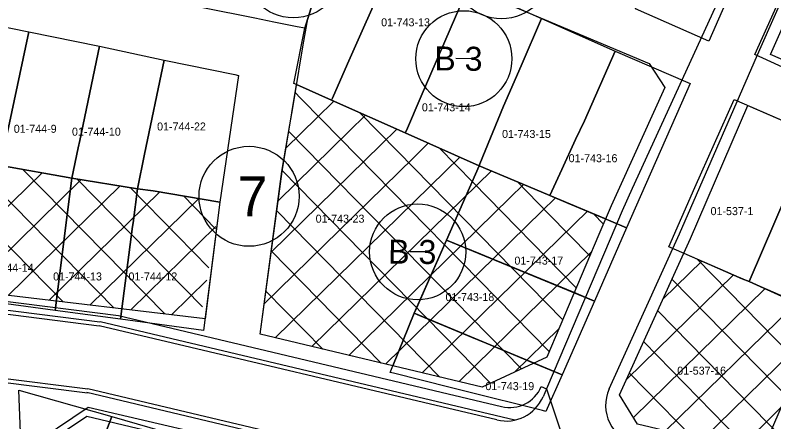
# Model space of a CAD drawing. Extents: x 413946 to 415528, y 4453939 to 4454944.
# Drawn here: x 414976 to 415070.8, y 4454449.6 to 4454500.5 of the extents above; entities that cross this region are included whole.
import ezdxf

# ---------------------------------------------------------------- set-up
doc = ezdxf.new("R2010")
doc.units = 0
for name, color, linetype in [('0_KADASTRO', 7, 'Continuous'), ('1_DÜZENLEME', 7, 'Continuous'), ('1_PLAN_DEĞİŞİKLİĞİ_ONAMA_SINIRI', 7, 'Continuous'), ('Level 27', 7, 'Continuous'), ('Level 28', 7, 'Continuous'), ('Level 29', 7, 'Continuous'), ('Level 32', 7, 'Continuous'), ('Level 34', 7, 'Continuous'), ('Level 57', 7, 'Continuous'), ('Level 58', 7, 'Continuous'), ('Level 62', 7, 'Continuous')]:
    doc.layers.add(name, color=color, linetype=linetype)

msp = doc.modelspace()

# ---------------------------------------------------------------- linework, layer by layer
at = {"layer": '0_KADASTRO'}
for points in [[(415053.526, 4454501.287), (415053.647, 4454501.564), (415056.611, 4454508.314), (415060.089, 4454516.235), (415061.598, 4454519.673), (415070.714, 4454515.564), (415062.675, 4454497.251)], [(414999.46, 4454501.4), (415000.783, 4454505.769), (415000.999, 4454506.48), (415003.5, 4454514.74), (415009.74, 4454512.95), (415015.95, 4454511.24), (415013.322, 4454502.539), (415012.206, 4454498.844), (415011.23, 4454499.04), (415008.331, 4454499.623), (415005.96, 4454500.1)], [(415010.831, 4454491.947), (415012.206, 4454498.844), (415013.322, 4454502.539), (415015.95, 4454511.24), (415023.668, 4454508.222), (415022.42, 4454505.4), (415017.55, 4454494.39), (415015.65, 4454490.095), (415015.543, 4454489.852), (415011.18, 4454491.792)], [(415015.543, 4454489.852), (415015.65, 4454490.095), (415017.55, 4454494.39), (415022.42, 4454505.4), (415023.668, 4454508.222), (415032.71, 4454504.157), (415031.57, 4454501.52), (415026.75, 4454490.37), (415024.892, 4454486.072), (415024.756, 4454485.756)], [(415024.756, 4454485.756), (415024.892, 4454486.072), (415026.75, 4454490.37), (415031.57, 4454501.52), (415032.71, 4454504.157), (415034.35, 4454503.42), (415041.78, 4454500.08), (415039.22, 4454494.14), (415037.04, 4454489.09), (415034.084, 4454481.889), (415033.987, 4454481.653)], [(415068.455, 4454495.571), (415072.492, 4454504.557), (415081.683, 4454500.61), (415081.14, 4454499.42), (415077.45, 4454491.43)], [(414965.358, 4454483.187), (414966.362, 4454488.021), (414966.55, 4454488.926), (414968.89, 4454500.2), (414977.709, 4454498.402), (414975.15, 4454486.42), (414975.008, 4454485.686), (414974.231, 4454481.676)], [(415033.987, 4454481.653), (415034.084, 4454481.889), (415037.04, 4454489.09), (415039.22, 4454494.14), (415041.78, 4454500.08), (415051, 4454496), (415047.14, 4454487.28), (415046.047, 4454484.925), (415044.3, 4454481.16), (415042.804, 4454477.937), (415040.144, 4454479.058)], [(414974.231, 4454481.676), (414975.008, 4454485.686), (414975.15, 4454486.42), (414977.709, 4454498.402), (414986.53, 4454496.61), (414984.071, 4454484.806), (414983.88, 4454483.892), (414983.09, 4454480.1)], [(414983.09, 4454480.1), (414983.88, 4454483.892), (414984.071, 4454484.806), (414986.53, 4454496.61), (414994.62, 4454494.87), (414992.186, 4454483.115), (414991.286, 4454478.771)], [(415042.804, 4454477.937), (415044.3, 4454481.16), (415046.047, 4454484.925), (415047.14, 4454487.28), (415051, 4454496), (415060.07, 4454492.06), (415060.344, 4454491.941), (415052.417, 4454473.885), (415052.1, 4454474.019), (415049.381, 4454475.165), (415045.077, 4454476.979)], [(414991.286, 4454478.771), (414992.186, 4454483.115), (414994.62, 4454494.87), (415003.45, 4454493.044), (415003.923, 4454492.946), (415001.59, 4454477.09), (414993.24, 4454478.51)], [(415006.61, 4454460.57), (415009.35, 4454480.93), (415011.18, 4454491.792), (415015.543, 4454489.852), (415024.756, 4454485.756), (415033.987, 4454481.653), (415029.907, 4454472.353), (415025.989, 4454463.44), (415025.883, 4454463.199), (415023.215, 4454456.611)], [(415057.69, 4454471.52), (415060.95, 4454478.93), (415065.84, 4454489.93), (415072.79, 4454486.95), (415075.692, 4454485.677), (415067.75, 4454467.15), (415066.87, 4454467.5), (415064.77, 4454468.42)], [(415067.75, 4454467.15), (415075.692, 4454485.677), (415084.758, 4454481.701), (415076.74, 4454463.07)], [(414972.081, 4454464.741), (414972.11, 4454464.98), (414973.586, 4454476.594), (414974.231, 4454481.676), (414983.09, 4454480.1), (414982.505, 4454475.494), (414980.986, 4454463.545)], [(415029.907, 4454472.353), (415033.987, 4454481.653), (415040.144, 4454479.058), (415042.804, 4454477.937), (415045.077, 4454476.979), (415049.381, 4454475.165), (415052.1, 4454474.019), (415052.417, 4454473.885), (415048.39, 4454464.712), (415045.869, 4454465.777), (415035.889, 4454469.892), (415034.199, 4454470.587)], [(414980.986, 4454463.545), (414982.505, 4454475.494), (414983.09, 4454480.1), (414991.286, 4454478.771), (414990.736, 4454474.513), (414990.678, 4454474.059), (414989.179, 4454462.444)], [(414989.179, 4454462.444), (414990.678, 4454474.059), (414990.736, 4454474.513), (414991.286, 4454478.771), (414993.24, 4454478.51), (415001.59, 4454477.09), (414999.56, 4454461.06)], [(415044.348, 4454455.506), (415025.883, 4454463.199), (415029.907, 4454472.353), (415048.39, 4454464.712)], [(415051.54, 4454452.98), (415059.577, 4454470.694), (415064.77, 4454468.42), (415066.87, 4454467.5), (415067.75, 4454467.15), (415076.74, 4454463.07), (415069.241, 4454445.645), (415053.79, 4454449.33)], [(415022.88, 4454455.784), (415023.215, 4454456.611), (415025.883, 4454463.199), (415026.514, 4454462.936), (415033.039, 4454460.218), (415034.844, 4454459.466), (415040.837, 4454456.969), (415044.348, 4454455.506), (415042.339, 4454450.928), (415041.913, 4454451.034), (415032.192, 4454453.46), (415030.364, 4454453.916), (415023.271, 4454455.686)], [(414976.99, 4454439.68), (414976.905, 4454441.941), (414976.47, 4454453.59), (414988.09, 4454450.27), (414983.71, 4454438.76), (414983.18, 4454437.36), (414982.59, 4454437.57)], [(414983.18, 4454437.36), (414983.71, 4454438.76), (414988.09, 4454450.27), (414995.98, 4454447.98), (414991.71, 4454437.66), (414990.46, 4454434.63)]]:
    msp.add_lwpolyline(points, close=True, dxfattribs=at)
at = {"layer": '1_DÜZENLEME'}
for p, q in [((414935.427, 4454468.565), (414986.575, 4454462.133)), ((414935.853, 4454468.008), (414986.513, 4454461.637)), ((415036.212, 4454449.853), (414986.513, 4454461.637)), ((415038.448, 4454449.837), (414986.628, 4454462.123)), ((414942.67, 4454459.088), (414985.087, 4454453.753)), ((414943.096, 4454458.53), (414985.024, 4454453.257)), ((415039.929, 4454440.75), (414985.087, 4454453.753)), ((415059.307, 4454435.642), (414984.971, 4454453.267))]:
    msp.add_line(p, q, dxfattribs=at)
msp.add_lwpolyline([(415042.389, 4454453.755), (415041.967, 4454452.762)], dxfattribs=at)
msp.add_arc((415037.365, 4454454.718), 5, 256.66157, 336.96465, dxfattribs=at)
at = {"layer": '1_PLAN_DEĞİŞİKLİĞİ_ONAMA_SINIRI'}
for p, q in [((414935.562, 4454469.642), (414988.897, 4454462.935)), ((415041.751, 4454454.026), (415042.389, 4454453.755))]:
    msp.add_line(p, q, dxfattribs=at)
for points in [[(414988.897, 4454462.935), (415036.79, 4454451.521)], [(415042.389, 4454453.755), (415045.679, 4454443.877), (415078.468, 4454435.986), (415078.129, 4454430.68), (415078.067, 4454429.715), (415028.701, 4454441.241), (414985.12, 4454451.416), (414977.335, 4454446.145), (414977.335, 4454442.344)]]:
    msp.add_lwpolyline(points, dxfattribs=at)
msp.add_arc((415037.788, 4454455.711), 4.307, 256.59684, 336.96326, dxfattribs=at)
at = {"layer": 'Level 27'}
for p, q in [((415019.237, 4454509.653), (415055.222, 4454494.424)), ((414999.744, 4454462.511), (414905.737, 4454473.656))]:
    msp.add_line(p, q, dxfattribs=at)
for points in [[(414960.05, 4454502.06), (414968.89, 4454500.2), (414977.709, 4454498.402), (414986.53, 4454496.61), (414994.62, 4454494.87), (415003.45, 4454493.044), (415003.92, 4454492.94), (415001.59, 4454477.09), (414999.744, 4454462.511)], [(415006.605, 4454460.572), (415009.347, 4454480.931), (415010.33, 4454486.775), (415010.688, 4454488.893)], [(415053.79, 4454449.33), (415051.544, 4454452.978)]]:
    msp.add_lwpolyline(points, dxfattribs=at)
at = {"layer": 'Level 28'}
for points in [[(415012.015, 4454496.781), (415012.559, 4454500.012), (415015.898, 4454511.067)], [(415010.944, 4454490.416), (415012.015, 4454496.781)], [(415010.688, 4454488.893), (415010.944, 4454490.416)], [(414978.399, 4454445.967), (414984.954, 4454450.311)]]:
    msp.add_lwpolyline(points, dxfattribs=at)
at = {"layer": 'Level 29'}
for points in [[(415070.414, 4454495.575), (415085.445, 4454529.505), (415087.807, 4454529.944)], [(415114.508, 4454476.135), (415105.966, 4454480.067), (415087.556, 4454488.117), (415070.414, 4454495.575)], [(415055.222, 4454494.424), (415057.208, 4454491.452), (415051.745, 4454479.406)], [(415051.544, 4454452.978), (415060.405, 4454472.529), (415067.579, 4454489.174)], [(415067.579, 4454489.174), (415084.758, 4454481.701), (415103.1, 4454473.68), (415112.194, 4454469.494)], [(415051.745, 4454479.406), (415050.486, 4454476.63), (415048.956, 4454473.033)], [(415048.956, 4454473.033), (415042.442, 4454457.712)], [(415034.378, 4454453.954), (415006.605, 4454460.572)], [(415042.442, 4454457.712), (415034.378, 4454453.954)], [(414984.954, 4454450.311), (415000.176, 4454446.684)]]:
    msp.add_lwpolyline(points, dxfattribs=at)
at = {"layer": 'Level 32'}
for p, q in [((415033.072, 4454495.03), (415031.072, 4454495.05)), ((415027.304, 4454470.866), (415025.304, 4454470.886))]:
    msp.add_line(p, q, dxfattribs=at)
for centre in [(415032.072, 4454495.04), (415026.304, 4454470.876)]:
    msp.add_circle(centre, 6, dxfattribs=at)
at = {"layer": 'Level 34'}
for p, q in [((415011.67, 4454490.12), (415011.007, 4454490.797)), ((415014.366, 4454487.369), (415011.67, 4454490.12)), ((415013.713, 4454487.639), (415015.837, 4454489.721)), ((415017.729, 4454485.975), (415019.769, 4454487.973)), ((415023.793, 4454483.462), (415019.067, 4454488.285)), ((415009.837, 4454483.842), (415013.713, 4454487.639)), ((415042.739, 4454458.41), (415014.367, 4454487.368)), ((415008.855, 4454477.28), (415017.73, 4454485.975)), ((415017.73, 4454485.975), (415017.73, 4454485.975)), ((415021.746, 4454484.31), (415023.701, 4454486.225)), ((415039.27, 4454456.234), (415010.186, 4454485.919)), ((415007.986, 4454470.828), (415021.746, 4454484.31)), ((415025.763, 4454482.645), (415027.632, 4454484.477)), ((414982.016, 4454464.613), (414963.51, 4454483.501)), ((415044.433, 4454462.395), (415023.794, 4454483.461)), ((415033.223, 4454479.553), (415028.989, 4454483.875)), ((414988.352, 4454463.861), (414970.23, 4454482.357)), ((415007.117, 4454464.378), (415025.762, 4454482.645)), ((415029.779, 4454480.981), (415031.565, 4454482.73)), ((414994.688, 4454463.11), (414976.977, 4454481.188)), ((414964.95, 4454466.636), (414979.368, 4454480.762)), ((415008.49, 4454460.123), (415029.779, 4454480.981)), ((415035.426, 4454454.442), (415009.366, 4454481.041)), ((415033.796, 4454479.316), (415035.521, 4454481.006)), ((414970.048, 4454466.031), (414984.205, 4454479.902)), ((414999.401, 4454464.015), (414983.758, 4454479.981)), ((415013.088, 4454459.027), (415033.796, 4454479.316)), ((415046.128, 4454466.381), (415033.222, 4454479.554)), ((415033.222, 4454479.554), (415033.222, 4454479.554)), ((415037.812, 4454477.652), (415039.517, 4454479.322)), ((415042.652, 4454475.646), (415038.721, 4454479.658)), ((414975.147, 4454465.427), (414989.125, 4454479.121)), ((414980.246, 4454464.822), (414994.072, 4454478.369)), ((415000.222, 4454468.893), (414990.432, 4454478.885)), ((414985.344, 4454464.218), (414998.942, 4454477.54)), ((415001.043, 4454473.77), (414997.031, 4454477.865)), ((415017.685, 4454457.932), (415037.812, 4454477.651)), ((415041.829, 4454475.987), (415043.515, 4454477.638)), ((415029.064, 4454455.22), (415008.686, 4454476.02)), ((415022.283, 4454456.836), (415041.829, 4454475.987)), ((415047.823, 4454470.367), (415042.651, 4454475.646)), ((415045.846, 4454474.322), (415047.511, 4454475.953)), ((415049.518, 4454474.353), (415048.259, 4454475.638)), ((414990.443, 4454463.613), (415001.089, 4454474.044)), ((415026.88, 4454455.741), (415045.846, 4454474.322)), ((415021.758, 4454456.961), (415008.009, 4454470.995)), ((415031.478, 4454454.645), (415048.036, 4454470.869)), ((415090.539, 4454440.023), (415061.174, 4454469.994)), ((415056.999, 4454465.014), (415061.802, 4454469.72)), ((415052.434, 4454454.942), (415065.76, 4454467.998)), ((414995.542, 4454463.009), (414999.961, 4454467.339)), ((415082.617, 4454442.393), (415058.092, 4454467.425)), ((415053.275, 4454450.166), (415069.73, 4454466.287)), ((415014.453, 4454458.702), (415007.332, 4454465.97)), ((415057.287, 4454448.497), (415073.685, 4454464.563)), ((415075.225, 4454444.222), (415056.321, 4454463.517)), ((415061.885, 4454447.401), (415077.641, 4454462.839)), ((415038.401, 4454455.829), (415043.955, 4454461.27)), ((415066.482, 4454446.306), (415081.597, 4454461.115)), ((415067.919, 4454445.963), (415054.55, 4454459.609)), ((415060.614, 4454447.704), (415052.778, 4454455.701))]:
    msp.add_line(p, q, dxfattribs=at)
at = {"layer": 'Level 57'}
for points in [[(415001.59, 4454477.09), (414993.24, 4454478.51), (414991.286, 4454478.771), (414983.09, 4454480.1), (414974.231, 4454481.676), (414965.358, 4454483.187), (414956.46, 4454484.7), (414947.613, 4454486.21), (414938.74, 4454487.721), (414929.868, 4454489.232), (414920.995, 4454490.744), (414892.553, 4454495.587)], [(415049.79, 4454474.992), (415042.804, 4454477.937), (415033.987, 4454481.653), (415024.756, 4454485.756), (415015.543, 4454489.852), (415011.176, 4454491.794)], [(415059.574, 4454470.695), (415064.77, 4454468.42), (415067.75, 4454467.15), (415085.85, 4454459.261), (415087.879, 4454463.778), (415106.003, 4454455.753)]]:
    msp.add_lwpolyline(points, dxfattribs=at)
at = {"layer": 'Level 58'}
for centre in [(415010.768, 4454506.403), (415036.779, 4454506.282), (415005.235, 4454477.827)]:
    msp.add_circle(centre, 6.25, dxfattribs=at)
at = {"layer": 'Level 62'}
for points in [[(415069.043, 4454496.183), (415084.394, 4454530.835)], [(415063.915, 4454502.376), (415053.128, 4454478.801)], [(415050.236, 4454453.725), (415059.033, 4454473.136), (415069.043, 4454496.183)], [(415053.128, 4454478.801), (415051.859, 4454476.027), (415050.342, 4454472.459)], [(415050.342, 4454472.459), (415042.389, 4454453.755)], [(415050.342, 4454472.459), (415050.342, 4454472.459)]]:
    msp.add_lwpolyline(points, dxfattribs=at)
msp.add_arc((415054.79, 4454451.661), 5, 155.61837, 256.59587, dxfattribs=at)

# ---------------------------------------------------------------- texts
at = {"layer": '0_KADASTRO'}
for s, p in [('01-743-13', (415021.741, 4454499.091)), ('01-743-14', (415026.83, 4454488.458)), ('01-744-22', (414993.74, 4454486.059)), ('01-744-9', (414975.83, 4454485.772)), ('01-744-10', (414983.101, 4454485.41)), ('01-743-15', (415036.849, 4454485.124)), ('01-743-16', (415045.17, 4454482.088)), ('01-537-1', (415062.906, 4454475.472)), ('01-743-23', (415013.557, 4454474.527)), ('01-743-17', (415038.394, 4454469.281)), ('01-744-14', (414972.213, 4454468.389)), ('01-744-13', (414980.747, 4454467.302)), ('01-744-12', (414990.163, 4454467.302)), ('01-743-18', (415029.783, 4454464.727)), ('01-537-16', (415058.743, 4454455.52)), ('01-743-19', (415034.765, 4454453.583))]:
    msp.add_text(s, height=1, dxfattribs=at).set_placement(p)
at = {"layer": 'Level 32'}
for p in [(415028.373, 4454493.578), (415022.604, 4454469.414)]:
    msp.add_text('B 3', height=3, rotation=359.4141, dxfattribs=at).set_placement(p)
at = {"layer": 'Level 58'}
msp.add_text('7', height=5, dxfattribs=at).set_placement((415003.817, 4454475.327))

doc.saveas('drawing.dxf')
